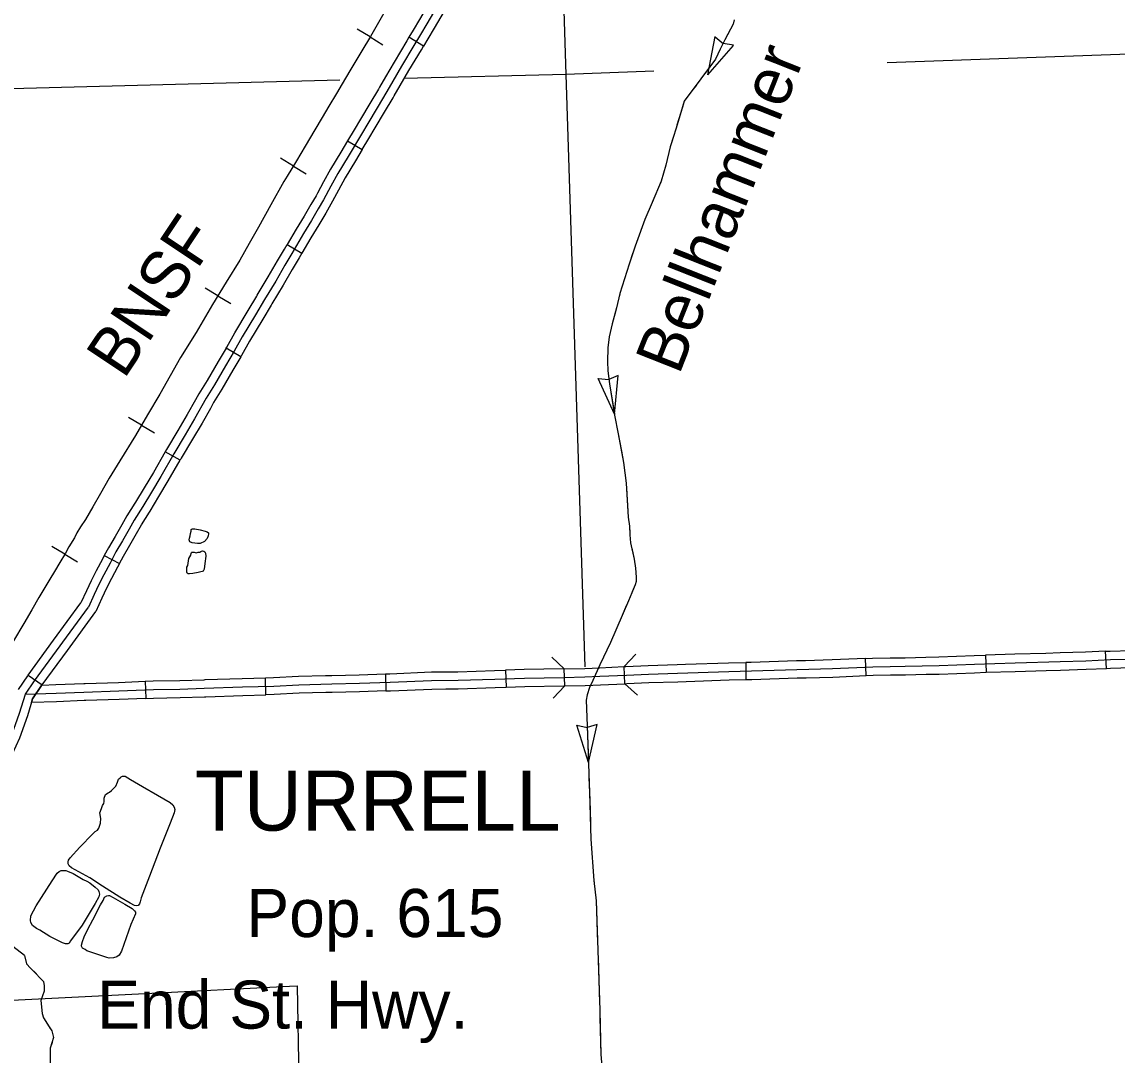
# Model space of a CAD drawing. Extents: x -117616 to 64730, y 54117 to 789866.
# Drawn here: x 63105.4 to 63297.9, y 54577.4 to 54758.9 of the extents above; entities that cross this region are included whole.
import ezdxf

# ---------------------------------------------------------------- set-up
doc = ezdxf.new("R2010")
doc.units = 0
for name, color, linetype in [('31', 7, 'Continuous'), ('35', 7, 'Continuous'), ('38', 7, 'Continuous'), ('40', 7, 'Continuous'), ('41', 7, 'Continuous'), ('43', 7, 'Continuous'), ('5', 7, 'Continuous'), ('6', 7, 'Continuous'), ('7', 7, 'Continuous')]:
    doc.layers.add(name, color=color, linetype=linetype)

msp = doc.modelspace()

# ---------------------------------------------------------------- linework, layer by layer
at = {"layer": '31'}
for p, q in [((63176, 54754.7), (63173.42, 54756.24)), ((63162.65, 54738.07), (63165.23, 54736.53)), ((63165.23, 54736.53), (63165.23, 54736.53)), ((63152.03, 54719.8), (63154.62, 54718.29)), ((63146.66, 54710.73), (63146.66, 54710.73)), ((63143.87, 54700.1), (63141.29, 54701.63)), ((63133.18, 54681.92), (63130.57, 54683.41)), ((63119.87, 54665.15), (63122.52, 54663.75)), ((63296.06, 54645.33), (63295.92, 54648.33)), ((63232.64, 54646.35), (63232.69, 54643.35)), ((63253.84, 54644.06), (63253.71, 54647.06)), ((63274.83, 54647.63), (63274.93, 54644.64)), ((63106.47, 54644.12), (63108.95, 54642.43)), ((63169.29, 54644.37), (63169.39, 54641.37)), ((63190.4, 54645.01), (63190.5, 54642.01)), ((63200.84, 54642.25), (63200.75, 54645.25)), ((63211.42, 54642.63), (63211.28, 54645.63)), ((63116.52, 54642.66), (63116.52, 54642.66)), ((63127.06, 54643.05), (63127.18, 54640.06)), ((63148.28, 54640.68), (63148.19, 54643.68))]:
    msp.add_line(p, q, dxfattribs=at)
for points in [[(63178.8, 54765.33), (63178.72, 54765.19), (63177.03, 54762.35), (63175.26, 54759.35), (63174.17, 54757.49), (63173.42, 54756.24)], [(63181.38, 54763.78), (63181.3, 54763.65), (63179.6, 54760.82), (63177.85, 54757.84), (63176.75, 54755.96), (63176, 54754.7)], [(63178.32, 54761.59), (63176.55, 54758.6), (63175.46, 54756.72), (63174.32, 54754.83), (63172.12, 54751.14), (63170.6, 54748.51), (63169.53, 54746.7), (63167.84, 54743.85), (63166.21, 54741.1), (63165.07, 54739.2), (63162.73, 54735.28), (63160.95, 54732.31), (63159.72, 54730.1), (63158.4, 54727.67), (63157.49, 54726.08), (63156.29, 54724.03), (63154.9, 54721.75), (63152.85, 54718.23), (63151.6, 54716.2), (63150, 54713.41), (63148.06, 54710.15), (63146.45, 54707.45), (63144.11, 54703.57), (63142.68, 54701.05), (63141.17, 54698.5), (63139.27, 54695.18), (63137.8, 54692.81), (63135.75, 54689.17), (63134.08, 54686.38), (63132.09, 54683.03), (63129.79, 54679.03), (63128.18, 54676.3), (63126.63, 54673.77), (63125.14, 54671.35), (63124.24, 54669.78), (63123.04, 54667.76), (63121.9, 54665.8), (63120.87, 54663.83), (63119.79, 54661.79), (63118.92, 54660.06), (63118.08, 54658.3), (63117.06, 54656.06)], [(63173.42, 54756.24), (63173.04, 54755.6), (63170.82, 54751.9), (63169.31, 54749.27), (63168.24, 54747.47), (63168.05, 54747.14)], [(63170.63, 54745.61), (63170.82, 54745.94), (63171.9, 54747.75), (63173.41, 54750.38), (63175.61, 54754.05), (63176, 54754.7)], [(63168.05, 54747.14), (63166.55, 54744.61), (63164.92, 54741.87), (63163.78, 54739.97), (63162.65, 54738.07)], [(63165.23, 54736.53), (63166.36, 54738.43), (63167.5, 54740.33), (63169.13, 54743.08), (63170.63, 54745.61)], [(63162.65, 54738.07), (63161.44, 54736.05), (63159.65, 54733.06), (63158.4, 54730.82), (63157.35, 54728.87)], [(63165.23, 54736.53), (63164.02, 54734.51), (63162.24, 54731.56), (63161.04, 54729.38), (63159.99, 54727.44)], [(63157.35, 54728.87), (63157.09, 54728.4), (63156.19, 54726.84), (63155, 54724.8), (63153.61, 54722.52), (63152.03, 54719.8)], [(63159.99, 54727.44), (63159.71, 54726.94), (63158.79, 54725.33), (63157.57, 54723.26), (63156.19, 54720.99), (63154.62, 54718.29)], [(63146.66, 54710.73), (63146.77, 54710.92), (63148.7, 54714.17), (63150.31, 54716.96), (63151.56, 54719), (63152.03, 54719.8)], [(63154.62, 54718.29), (63154.14, 54717.46), (63152.89, 54715.43), (63151.29, 54712.65), (63149.35, 54709.38), (63149.23, 54709.19)], [(63141.29, 54701.63), (63141.39, 54701.8), (63142.82, 54704.32), (63145.17, 54708.22), (63146.66, 54710.73)], [(63149.23, 54709.19), (63147.74, 54706.68), (63145.41, 54702.81), (63143.98, 54700.29), (63143.87, 54700.1)], [(63141.29, 54701.63), (63139.87, 54699.26), (63137.98, 54695.94), (63136.51, 54693.58), (63135.91, 54692.51)], [(63143.87, 54700.1), (63142.46, 54697.75), (63140.56, 54694.41), (63139.09, 54692.05), (63138.52, 54691.03)], [(63135.91, 54692.51), (63134.45, 54689.93), (63132.79, 54687.15), (63130.79, 54683.79), (63130.57, 54683.41)], [(63138.52, 54691.03), (63137.05, 54688.42), (63135.37, 54685.62), (63133.38, 54682.28), (63133.18, 54681.92)], [(63130.57, 54683.41), (63128.49, 54679.78), (63126.9, 54677.07), (63125.35, 54674.55), (63125.23, 54674.36)], [(63127.79, 54672.78), (63127.91, 54672.98), (63129.47, 54675.53), (63131.09, 54678.27), (63133.18, 54681.92)], [(63125.23, 54674.36), (63123.85, 54672.12), (63122.94, 54670.54), (63121.75, 54668.52), (63120.59, 54666.52), (63119.87, 54665.15)], [(63122.52, 54663.75), (63123.22, 54665.07), (63124.34, 54667), (63125.53, 54669.02), (63126.43, 54670.58), (63127.79, 54672.78)], [(63119.87, 54665.15), (63119.54, 54664.53), (63118.45, 54662.48), (63117.58, 54660.72), (63116.72, 54658.93), (63115.76, 54656.82)], [(63122.52, 54663.75), (63122.19, 54663.13), (63121.12, 54661.1), (63120.27, 54659.4), (63119.44, 54657.66), (63118.36, 54655.3)], [(63106.01, 54640.8), (63107.62, 54643.16), (63117.06, 54656.06)], [(63110.96, 54650.26), (63115.76, 54656.82)], [(63113.38, 54648.49), (63118.36, 54655.3)], [(63106.47, 54644.12), (63110.96, 54650.26)], [(63108.95, 54642.43), (63113.38, 54648.49)], [(63285.39, 54647.96), (63279.96, 54647.8), (63274.83, 54647.63)], [(63295.92, 54648.33), (63292.41, 54648.17), (63287.91, 54648.04), (63285.39, 54647.96)], [(63295.92, 54648.33), (63296.71, 54648.36), (63300.33, 54648.46), (63306.48, 54648.71)], [(63106.01, 54640.8), (63111.4, 54640.97), (63116.29, 54641.16), (63122.43, 54641.37), (63128.5, 54641.61), (63133.16, 54641.68), (63137.45, 54641.84), (63144.17, 54642.06), (63149.69, 54642.22), (63154.06, 54642.44), (63159.89, 54642.59), (63164.71, 54642.71), (63170.14, 54642.9), (63177.41, 54643.19), (63182.08, 54643.24), (63188.53, 54643.44), (63193.75, 54643.62), (63200.65, 54643.75), (63204.38, 54643.82), (63207.02, 54643.93), (63211.66, 54644.15), (63215.57, 54644.33), (63220.66, 54644.49), (63229.67, 54644.8), (63233.67, 54644.87), (63241.64, 54645.14), (63247.91, 54645.31), (63254.99, 54645.61), (63258.07, 54645.67), (63260.71, 54645.69), (63266.64, 54645.83), (63272.85, 54646.07), (63280, 54646.3), (63287.96, 54646.54), (63292.47, 54646.67), (63296.76, 54646.87), (63300.38, 54646.96)], [(63211.28, 54645.63), (63211.59, 54645.64), (63215.51, 54645.83), (63220.61, 54645.99), (63222.06, 54646.04)], [(63222.06, 54646.04), (63229.63, 54646.3), (63232.64, 54646.35)], [(63243.18, 54646.68), (63241.59, 54646.64), (63233.63, 54646.37), (63232.64, 54646.35)], [(63253.71, 54647.06), (63247.85, 54646.81), (63243.18, 54646.68)], [(63253.71, 54647.06), (63254.94, 54647.11), (63258.05, 54647.17), (63260.69, 54647.19), (63264.29, 54647.28)], [(63264.29, 54647.28), (63266.59, 54647.33), (63272.8, 54647.57), (63274.83, 54647.63)], [(63104.78, 54641.64), (63106.4, 54644.02), (63106.47, 54644.12)], [(63148.19, 54643.68), (63149.63, 54643.72), (63154, 54643.94), (63158.75, 54644.06)], [(63158.75, 54644.06), (63159.85, 54644.09), (63164.67, 54644.21), (63169.29, 54644.37)], [(63169.29, 54644.37), (63170.09, 54644.39), (63177.37, 54644.69), (63179.87, 54644.71)], [(63179.87, 54644.71), (63182.05, 54644.74), (63188.48, 54644.94), (63190.4, 54645.01)], [(63200.75, 54645.25), (63200.62, 54645.25), (63193.71, 54645.12), (63190.4, 54645.01)], [(63200.75, 54645.25), (63204.33, 54645.32), (63206.96, 54645.43), (63211.28, 54645.63)], [(63243.26, 54643.69), (63247.96, 54643.81), (63253.84, 54644.06)], [(63253.84, 54644.06), (63255.03, 54644.12), (63258.09, 54644.17), (63260.74, 54644.19), (63264.37, 54644.28)], [(63264.37, 54644.28), (63266.68, 54644.33), (63272.9, 54644.57), (63274.93, 54644.64)], [(63274.93, 54644.64), (63280.05, 54644.8), (63285.48, 54644.97)], [(63285.48, 54644.97), (63288, 54645.04), (63292.52, 54645.17), (63296.06, 54645.33)], [(63296.06, 54645.33), (63296.81, 54645.37), (63300.43, 54645.46), (63306.6, 54645.71)], [(63107.07, 54639.33), (63107.25, 54639.95), (63108.85, 54642.29), (63108.92, 54642.39)], [(63108.95, 54642.43), (63108.85, 54642.29), (63107.25, 54639.95)], [(63108.92, 54642.39), (63111.35, 54642.47), (63116.24, 54642.65), (63116.52, 54642.66)], [(63116.52, 54642.66), (63122.38, 54642.87), (63127.06, 54643.05)], [(63127.06, 54643.05), (63128.46, 54643.11), (63133.12, 54643.18), (63137.4, 54643.34), (63137.63, 54643.35)], [(63137.63, 54643.35), (63144.12, 54643.56), (63148.19, 54643.68)], [(63179.91, 54641.71), (63182.11, 54641.74), (63188.58, 54641.94), (63190.5, 54642.01)], [(63190.5, 54642.01), (63193.79, 54642.12), (63200.68, 54642.25), (63200.84, 54642.25)], [(63200.84, 54642.25), (63204.42, 54642.32), (63207.09, 54642.43), (63211.42, 54642.63)], [(63211.42, 54642.63), (63211.73, 54642.65), (63215.63, 54642.83), (63220.71, 54642.99), (63222.16, 54643.04)], [(63222.16, 54643.04), (63229.71, 54643.3), (63232.69, 54643.35)], [(63232.69, 54643.35), (63233.71, 54643.37), (63241.68, 54643.64), (63243.26, 54643.69)], [(63094.43, 54623.46), (63096.14, 54624.85), (63098.89, 54627.2), (63100.66, 54628.69), (63102.38, 54631.04), (63103.58, 54633.62), (63104.96, 54637.46), (63106.01, 54640.8)], [(63107.25, 54639.95), (63106.38, 54636.98), (63104.97, 54633.05), (63103.68, 54630.27), (63103.3, 54629.76)], [(63127.18, 54640.06), (63122.49, 54639.87), (63116.62, 54639.67)], [(63127.18, 54640.06), (63128.54, 54640.11), (63133.2, 54640.18), (63137.5, 54640.35), (63137.72, 54640.35)], [(63137.72, 54640.35), (63144.22, 54640.56), (63148.28, 54640.68)], [(63158.82, 54641.06), (63154.12, 54640.94), (63149.75, 54640.73), (63148.28, 54640.68)], [(63169.39, 54641.37), (63164.75, 54641.22), (63159.93, 54641.09), (63158.82, 54641.06)], [(63169.39, 54641.37), (63170.2, 54641.4), (63177.45, 54641.69), (63179.91, 54641.71)], [(63116.62, 54639.67), (63116.35, 54639.66), (63111.45, 54639.47), (63107.07, 54639.33)]]:
    msp.add_lwpolyline(points, dxfattribs=at)
at = {"layer": '35'}
for points in [[(63135.79, 54669.83), (63136.74, 54669.66), (63137.6, 54669.47), (63137.98, 54669.35), (63138.17, 54669.14), (63138.17, 54668.95), (63138.13, 54668.63), (63137.96, 54668.13), (63137.5, 54667.61), (63136.74, 54667.29), (63136.28, 54667.25), (63135.31, 54667.4), (63134.89, 54667.58), (63134.83, 54667.73), (63134.81, 54667.94), (63134.87, 54668.24), (63134.99, 54668.64), (63135.02, 54669.06), (63135.14, 54669.47), (63135.16, 54669.73), (63135.29, 54669.83), (63135.35, 54669.85), (63135.6, 54669.85), (63135.79, 54669.83)], [(63134.55, 54663.42), (63134.73, 54664.61), (63135.08, 54665.24), (63135.11, 54665.52), (63135.21, 54665.68), (63135.27, 54665.73), (63135.57, 54665.74), (63135.64, 54665.73), (63136.02, 54665.66), (63136.37, 54665.73), (63136.65, 54665.75), (63136.84, 54665.87), (63136.97, 54665.94), (63137.16, 54665.97), (63137.35, 54665.94), (63137.54, 54665.8), (63137.68, 54665.55), (63137.69, 54665.04), (63137.55, 54663.78), (63137.4, 54662.77), (63137.3, 54662.52), (63137.27, 54662.43), (63137.06, 54662.35), (63136.39, 54662.16), (63135.45, 54661.98), (63134.87, 54661.93), (63134.64, 54661.97), (63134.45, 54662.07), (63134.37, 54662.25), (63134.38, 54662.71), (63134.39, 54663.13), (63134.55, 54663.42)], [(63123.51, 54626.37), (63124.49, 54625.8), (63126.56, 54624.58), (63129.22, 54623.06), (63131.46, 54621.77), (63131.91, 54621.34), (63132.17, 54620.94), (63132.29, 54620.51), (63132.17, 54619.91), (63131.44, 54618.1), (63129.7, 54613.72), (63127.82, 54608.79), (63126.37, 54605), (63126.2, 54604.28), (63126.06, 54603.92), (63125.82, 54603.66), (63125.51, 54603.62), (63125.15, 54603.64), (63124.44, 54604.04), (63122.58, 54605.09), (63119.53, 54607.07), (63117.3, 54608.5), (63114.08, 54610.29), (63113.68, 54610.62), (63113.51, 54610.95), (63113.51, 54611.33), (63113.56, 54611.64), (63113.87, 54612.05), (63115.58, 54613.93), (63117.87, 54616.27), (63118.27, 54616.67), (63118.65, 54616.91), (63118.92, 54617.27), (63119.2, 54618.1), (63119.25, 54618.93), (63119.08, 54619.91), (63119.37, 54620.7), (63119.53, 54621.22), (63119.8, 54621.58), (63119.82, 54621.94), (63119.87, 54622.51), (63120.08, 54623.18), (63120.56, 54623.46), (63120.8, 54623.56), (63121.15, 54623.84), (63121.46, 54624.22), (63121.87, 54624.63), (63122.18, 54625.32), (63122.39, 54625.84), (63122.68, 54626.11), (63122.84, 54626.27), (63123.06, 54626.37), (63123.32, 54626.39), (63123.51, 54626.37)], [(63105.85, 54594.85), (63103.81, 54596.46), (63102.29, 54597.61), (63101.05, 54599.04), (63100.07, 54600.46), (63099.89, 54601.35), (63099.63, 54605.89), (63099.36, 54613.98), (63099.41, 54622.02)], [(63113.42, 54609.71), (63114.37, 54609.29), (63116.14, 54608.23), (63116.82, 54607.93), (63117.3, 54607.63), (63118.25, 54606.88), (63118.77, 54606.39), (63118.89, 54606.09), (63119, 54605.67), (63118.92, 54605.18), (63118.28, 54603.98), (63115.99, 54600.21), (63113.92, 54597.43), (63113.66, 54597.01), (63113.43, 54596.9), (63113.05, 54596.94), (63112.53, 54597.09), (63110.27, 54598.22), (63108.54, 54599.31), (63107.94, 54599.61), (63107.26, 54600.14), (63106.96, 54600.66), (63106.88, 54601.04), (63106.96, 54601.83), (63107.86, 54603.6), (63110.68, 54608.01), (63111.59, 54609.33), (63111.9, 54609.63), (63112.28, 54609.8), (63112.73, 54609.83), (63113.13, 54609.82), (63113.42, 54609.71)], [(63120.79, 54605.39), (63121.44, 54605.04), (63123.49, 54603.87), (63124.78, 54603.11), (63125.19, 54602.73), (63125.36, 54602.49), (63125.33, 54602.17), (63124.54, 54600.29), (63122.9, 54595.6), (63122.49, 54594.93), (63122.08, 54594.63), (63121.46, 54594.46), (63120.73, 54594.37), (63120.32, 54594.49), (63119.59, 54594.75), (63118.04, 54595.25), (63116.81, 54595.66), (63116.48, 54595.92), (63116.04, 54596.16), (63115.87, 54596.48), (63115.87, 54596.69), (63116.04, 54597.33), (63116.31, 54598.15), (63116.95, 54599.5), (63117.83, 54601.14), (63119.21, 54603.78), (63119.68, 54604.51), (63119.91, 54605.1), (63120.29, 54605.34), (63120.62, 54605.39), (63120.79, 54605.39)]]:
    msp.add_lwpolyline(points, dxfattribs=at)
at = {"layer": '38'}
for points in [[(63211.28, 54645.63), (63213.3, 54647.85)], [(63198.56, 54647.3), (63200.75, 54645.25)], [(63200.84, 54642.25), (63198.79, 54640.07)], [(63213.64, 54640.61), (63211.42, 54642.63)]]:
    msp.add_lwpolyline(points, dxfattribs=at)
at = {"layer": '40'}
for p, q in [((63166.61, 54756.3), (63164.35, 54757.68)), ((63166.61, 54756.3), (63168.86, 54754.92)), ((63153.11, 54733.61), (63150.85, 54734.99)), ((63153.11, 54733.61), (63155.37, 54732.24)), ((63139.84, 54710.79), (63137.58, 54712.16)), ((63139.84, 54710.79), (63142.1, 54709.43)), ((63126.42, 54688.07), (63124.14, 54689.4)), ((63126.42, 54688.07), (63128.69, 54686.74)), ((63112.9, 54665.4), (63110.63, 54666.74)), ((63112.9, 54665.4), (63115.18, 54664.06))]:
    msp.add_line(p, q, dxfattribs=at)
for points in [[(63199.71, 54812.32), (63198.24, 54809.82), (63195.8, 54805.7), (63192.43, 54800), (63189.96, 54795.8), (63186.58, 54790.13), (63183.94, 54785.76), (63181.33, 54781.29), (63178.86, 54777.12), (63175.75, 54771.8), (63174.05, 54768.92), (63172.61, 54766.4), (63170.32, 54762.72), (63168.3, 54759.26), (63166.65, 54756.38), (63165.13, 54753.88), (63163.01, 54750.33), (63161.69, 54748.09), (63160.72, 54746.39), (63159.37, 54744.13), (63158.2, 54742.13), (63156.88, 54739.99)], [(63168.3, 54759.26), (63166.65, 54756.38), (63165.13, 54753.88), (63163.01, 54750.33), (63161.69, 54748.09), (63160.72, 54746.39), (63159.37, 54744.13), (63158.2, 54742.13), (63156.88, 54739.99)], [(63156.88, 54739.99), (63155.18, 54737.08), (63153.68, 54734.55), (63152.04, 54731.85), (63151.42, 54730.88), (63149.16, 54726.77), (63146.99, 54722.89), (63145.31, 54720.01), (63143.67, 54717.1), (63141.29, 54713.19), (63138.91, 54709.26), (63136.04, 54704.35), (63133.25, 54699.94), (63129.61, 54693.54), (63127.47, 54689.87), (63125.35, 54686.25), (63122.59, 54681.82), (63120.74, 54678.73), (63119.22, 54676.06), (63117.84, 54673.71), (63116.58, 54671.51), (63115.67, 54670.18), (63115.05, 54669.16), (63114.61, 54668.27), (63113.64, 54666.66), (63113.02, 54665.6), (63112.06, 54663.96), (63111.12, 54662.37), (63110.29, 54661.02), (63109.38, 54659.52), (63108.33, 54657.76), (63107.1, 54655.64), (63105.72, 54653.2), (63103.9, 54650.15)], [(63156.88, 54739.99), (63155.18, 54737.08), (63153.68, 54734.55), (63152.04, 54731.85), (63151.42, 54730.88), (63149.16, 54726.77), (63146.99, 54722.89), (63145.31, 54720.01), (63143.67, 54717.1), (63141.29, 54713.19), (63138.91, 54709.26), (63136.04, 54704.35), (63133.25, 54699.94), (63129.61, 54693.54), (63127.47, 54689.87), (63125.35, 54686.25), (63122.59, 54681.82), (63120.74, 54678.73), (63119.22, 54676.06), (63117.84, 54673.71), (63116.58, 54671.51), (63115.67, 54670.18), (63115.05, 54669.16), (63114.61, 54668.27), (63113.64, 54666.66), (63113.02, 54665.6), (63112.06, 54663.96), (63111.12, 54662.37), (63110.29, 54661.02), (63109.38, 54659.52), (63108.33, 54657.76), (63107.1, 54655.64), (63105.72, 54653.2), (63103.9, 54650.15)]]:
    msp.add_lwpolyline(points, dxfattribs=at)
at = {"layer": '43'}
for p, q in [((63225.99, 54749.62), (63227.29, 54756.36)), ((63227.26, 54756.34), (63228.66, 54755.17)), ((63225.99, 54749.62), (63230.49, 54754.8)), ((63230.48, 54754.84), (63228.68, 54755.16)), ((63206.72, 54696.25), (63208.57, 54696.08)), ((63209.56, 54690), (63206.72, 54696.25)), ((63210.22, 54696.83), (63208.6, 54696.08)), ((63209.56, 54690), (63210.22, 54696.83)), ((63204.99, 54628.77), (63202.95, 54635.33)), ((63202.95, 54635.33), (63204.74, 54634.92)), ((63206.51, 54635.47), (63204.76, 54634.92)), ((63204.99, 54628.77), (63206.51, 54635.47))]:
    msp.add_line(p, q, dxfattribs=at)
for points in [[(63230.62, 54759.3), (63230.43, 54758.55), (63228.95, 54755.78), (63228.18, 54754.13), (63227.35, 54752.42), (63224.76, 54748.93), (63223.39, 54747.1), (63222.45, 54745.89), (63221.81, 54744.99), (63221.24, 54743.03), (63220.39, 54740.28), (63219.39, 54736.98), (63218.62, 54733.79), (63217.78, 54730.93), (63216.2, 54727.18), (63214.93, 54724.22), (63213.2, 54719.52), (63212.18, 54716.37), (63210.53, 54711.2), (63209.9, 54708.68), (63209.15, 54705.9), (63208.61, 54703.59), (63208.42, 54701.67), (63208.36, 54699.27), (63208.4, 54697.6), (63208.67, 54695.33), (63209.59, 54689.84), (63210.2, 54686.52), (63211.18, 54681.5), (63211.61, 54677.87), (63211.95, 54671.92), (63212.22, 54670.34), (63212.28, 54668.79), (63212.38, 54667.4), (63213.05, 54664.52), (63213.26, 54662.95), (63213.41, 54661.37), (63213.38, 54660.6), (63213.18, 54659.99), (63212.01, 54657.22), (63210.95, 54654.63), (63208.86, 54649.87), (63207.01, 54645.97), (63205.74, 54643.18), (63205.19, 54641.95), (63204.78, 54640.68), (63204.59, 54639.76), (63204.74, 54635.25), (63205.19, 54623.53), (63205.4, 54615.33), (63205.97, 54608.03), (63206.36, 54604.49), (63206.63, 54595.79), (63206.99, 54585.19), (63207.19, 54577.49), (63207.38, 54574.68)], [(63229.46, 54756.73), (63228.95, 54755.78), (63228.18, 54754.13), (63227.35, 54752.42), (63225.49, 54749.92)], [(63223.92, 54747.8), (63223.39, 54747.1), (63222.45, 54745.89), (63221.81, 54744.99), (63221.68, 54744.56)], [(63221.68, 54744.56), (63221.24, 54743.03), (63220.54, 54740.77)], [(63219.77, 54738.25), (63219.39, 54736.98), (63218.62, 54733.79), (63217.78, 54730.93), (63217.65, 54730.62)], [(63216.63, 54728.19), (63216.2, 54727.18), (63214.93, 54724.22), (63213.68, 54720.84)], [(63212.82, 54718.35), (63212.18, 54716.37), (63210.53, 54711.2), (63210.43, 54710.79)], [(63209.79, 54708.23), (63209.15, 54705.9), (63208.61, 54703.59), (63208.42, 54701.67), (63208.39, 54700.47)], [(63208.4, 54697.83), (63208.4, 54697.6), (63208.67, 54695.33), (63209.56, 54690)], [(63210.04, 54687.4), (63210.2, 54686.52), (63210.78, 54683.51)], [(63210.78, 54683.51), (63211.18, 54681.5), (63211.4, 54679.61)], [(63211.66, 54676.98), (63211.95, 54671.92), (63212.22, 54670.34), (63212.27, 54669.09)], [(63212.6, 54666.48), (63213.05, 54664.52), (63213.26, 54662.95), (63213.41, 54661.37), (63213.38, 54660.6), (63213.18, 54659.99), (63212.66, 54658.77)], [(63211.65, 54656.34), (63210.95, 54654.63), (63208.86, 54649.87), (63208.48, 54649.08)], [(63207.35, 54646.69), (63207.01, 54645.97), (63206.76, 54645.42)], [(63205.38, 54642.36), (63205.19, 54641.95), (63204.78, 54640.68), (63204.59, 54639.76), (63204.6, 54639.32)], [(63204.69, 54636.69), (63204.74, 54635.25), (63204.99, 54628.77)], [(63205.09, 54626.13), (63205.19, 54623.53), (63205.23, 54622.18)], [(63205.23, 54622.18), (63205.33, 54618.22)], [(63205.4, 54615.58), (63205.4, 54615.33), (63205.97, 54608.03), (63206, 54607.68)], [(63206.3, 54605.06), (63206.36, 54604.49), (63206.59, 54597.15)], [(63105.85, 54594.85), (63106.2, 54593.41), (63106.87, 54592.65), (63107.97, 54591.6), (63108.48, 54590.97), (63109.15, 54590.29), (63109.28, 54589.53), (63109.28, 54588.6), (63109.02, 54587.8), (63108.73, 54586.96), (63108.94, 54584.68), (63109.19, 54583.88), (63110.16, 54582.32), (63110.63, 54581.64), (63110.96, 54580.46), (63110.33, 54578.56), (63110.33, 54575.19)], [(63105.85, 54594.85), (63106.2, 54593.41), (63106.87, 54592.65), (63107.93, 54591.64)], [(63206.68, 54594.51), (63206.94, 54586.59)], [(63109.28, 54589.49), (63109.28, 54588.6), (63109.02, 54587.8), (63108.73, 54586.96), (63108.94, 54584.68), (63109.19, 54583.88), (63110.16, 54582.32), (63110.35, 54582.04)], [(63207.02, 54583.95), (63207.19, 54577.49), (63207.29, 54576.04)], [(63110.67, 54579.58), (63110.33, 54578.56), (63110.33, 54575.19), (63110.33, 54572.53), (63110.35, 54571.71)]]:
    msp.add_lwpolyline(points, dxfattribs=at)
at = {"layer": '5'}
for points in [[(63199.61, 54794.55), (63201.01, 54749.72)], [(63304.97, 54753.48), (63257.51, 54751.77)], [(63201.01, 54749.72), (63172.6, 54748.98)], [(63216.49, 54750.28), (63201.01, 54749.72)], [(63201.01, 54749.72), (63204.37, 54645.57)], [(63161.28, 54748.68), (63094.5, 54746.94)]]:
    msp.add_lwpolyline(points, dxfattribs=at)
at = {"layer": '7'}
for p, q in [((63103.63, 54587), (63127.04, 54588.18)), ((63127.04, 54588.18), (63152.41, 54589.47)), ((63152.41, 54589.47), (63153.79, 54589.54)), ((63153.79, 54589.54), (63154.33, 54556.59))]:
    msp.add_line(p, q, dxfattribs=at)

# ---------------------------------------------------------------- texts
at = {"layer": '35'}
msp.add_text('Bellhammer', height=8.448, rotation=68.4259, dxfattribs=at).set_placement((63220.91, 54696.72))
at = {"layer": '40'}
msp.add_text('BNSF', height=8.448, rotation=56.3317, dxfattribs=at).set_placement((63123.31, 54695.98))
at = {"layer": '41'}
msp.add_text('End St. Hwy.', height=8.448, dxfattribs=at).set_placement((63118.6, 54582.01))
at = {"layer": '6'}
for s, height, p in [('TURRELL', 10.56, (63135.78, 54616.81)), ('Pop. 615', 8.448, (63144.83, 54598.11))]:
    msp.add_text(s, height=height, dxfattribs=at).set_placement(p)

doc.saveas('drawing.dxf')
